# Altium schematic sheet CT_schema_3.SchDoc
size 360 x 214 mm
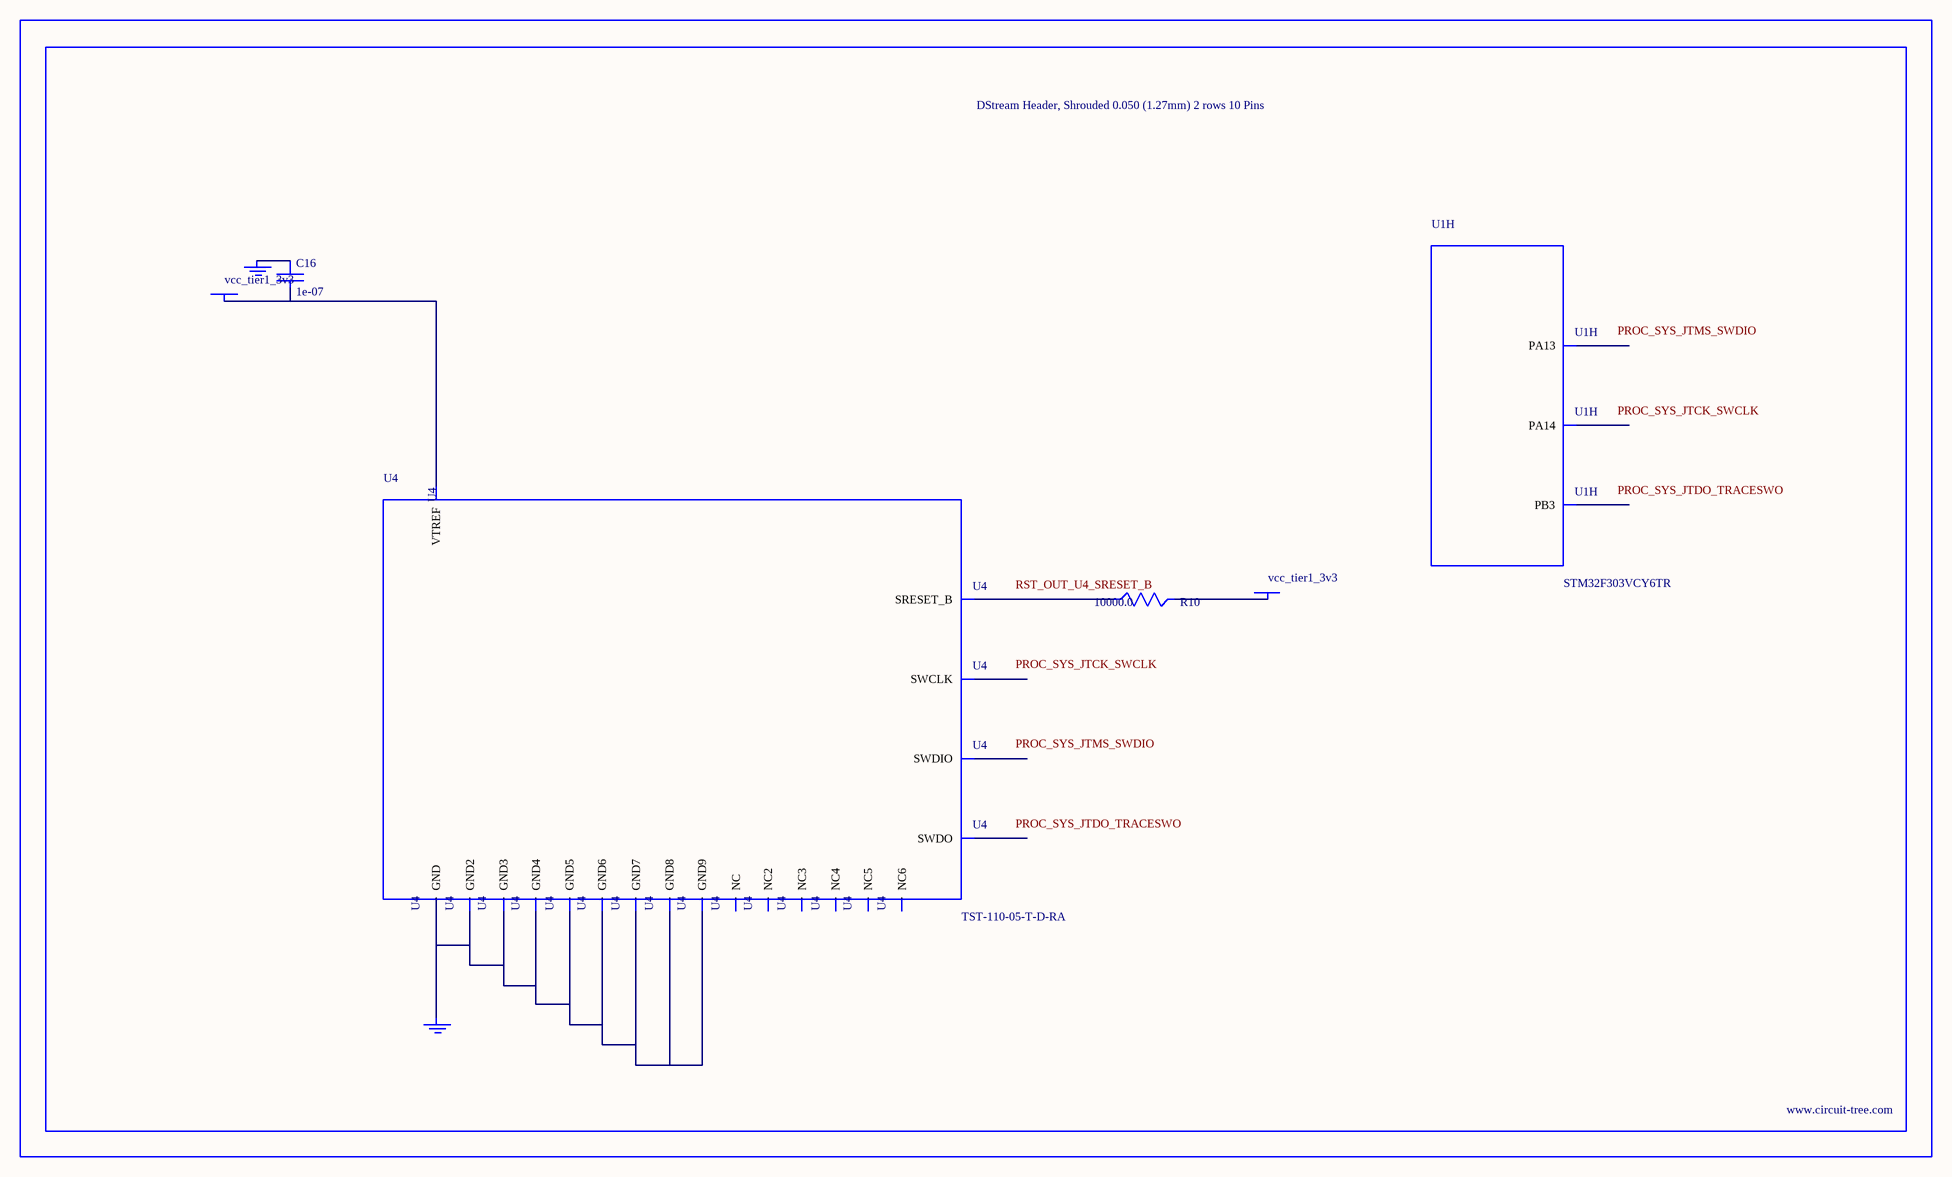
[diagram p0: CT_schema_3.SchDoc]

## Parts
BORDER2  (no value)
C16  1e-07  [C0402]
GND_INSTANCE_2_0  (no value)
GND_INSTANCE_2_1  (no value)
POWER_INSTANCE_2_0  vcc_tier1_3v3
POWER_INSTANCE_2_1  vcc_tier1_3v3
R10  10000.0  [R0603]
U1  STM32F303VCY6TR  [WLCSP100]  (part H of 10)
U4  TST-110-05-T-D-RA  [TST-110-05-T-D-RA]

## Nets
NetC16_1: C16.1 GND_INSTANCE_2_0.0(GND)
NetC16_2: C16.2 POWER_INSTANCE_2_0.0(PWR) U4.1(VTREF)
NetGND_INSTANCE_2_1_0: GND_INSTANCE_2_1.0(GND) U4.4(GND) U4.6(GND2) U4.8(GND3) U4.10(GND4) U4.12(GND5) U4.14(GND6) U4.16(GND7) U4.18(GND8) U4.20(GND9)
NetPOWER_INSTANCE_2_1_0: POWER_INSTANCE_2_1.0(PWR) R10.2
NetR10_1: R10.1 U4.15(SRESET_B)

Not connected (* = marked no-connect by the designer): U1 A5(PB3) C2(PA14) E3(PA13); U4 2(NC) 3(NC2) 5(NC3) 7(SWDIO) 9(SWCLK) 11(NC4) 13(SWDO) 17(NC5) 19(NC6)

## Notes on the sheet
- Labels drawn without touching a wire or pin: PROC_SYS_JTCK_SWCLK, PROC_SYS_JTDO_TRACESWO, PROC_SYS_JTMS_SWDIO, RST_OUT_U4_SRESET_B

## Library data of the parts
BORDER2 = BORDER_PAGE2
C16 = C0402C104K3RACTU
GND_INSTANCE_2_0 GND_INSTANCE_2_1 = GND
POWER_INSTANCE_2_0 POWER_INSTANCE_2_1 = PWR
R10 = RC0603JR-0710KL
